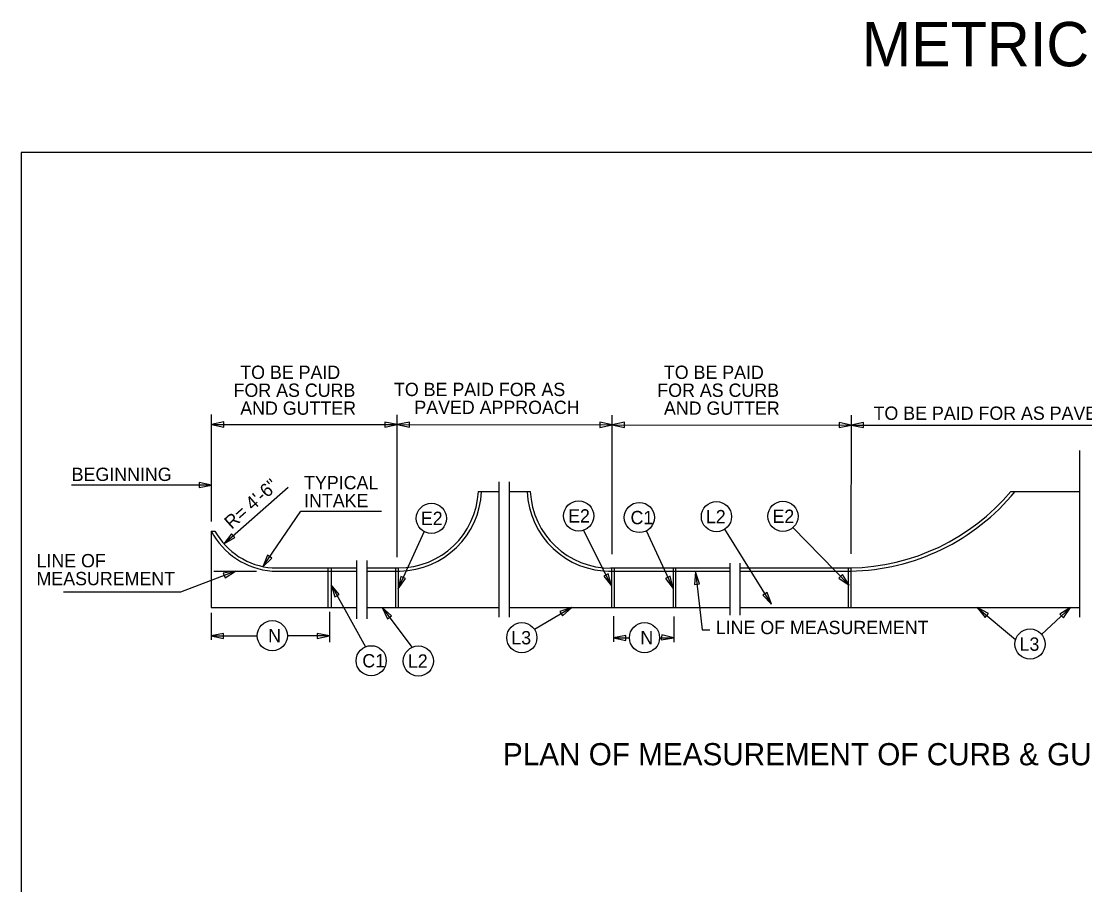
# Model space of a CAD drawing. Extents: x -439.1 to -407.9, y -458.1 to -436.2.
# Drawn here: x -439.11 to -427.13, y -445.93 to -436.2 of the extents above; entities that cross this region are included whole.
import ezdxf

# ---------------------------------------------------------------- set-up
doc = ezdxf.new("R2010")
doc.units = 0
for name, color, linetype in [('Draft_Named_Boundary', 7, 'Continuous'), ('Level 4', 7, 'Continuous'), ('Level 46', 7, 'Continuous')]:
    doc.layers.add(name, color=color, linetype=linetype)

msp = doc.modelspace()

# ---------------------------------------------------------------- linework, layer by layer
at = {"layer": 'Draft_Named_Boundary'}
msp.add_lwpolyline([(-439.109, -458.051), (-407.859, -458.051), (-407.859, -437.676), (-439.109, -437.676)], close=True, dxfattribs=at)
at = {"layer": 'Level 4'}
for p, q in [((-436.966, -441.833), (-436.965, -440.63)), ((-434.875, -442.238), (-434.874, -440.631)), ((-432.453, -442.203), (-432.451, -440.636)), ((-429.76, -442.198), (-429.758, -440.638)), ((-436.965, -440.741), (-434.874, -440.743)), ((-434.874, -440.743), (-432.452, -440.745)), ((-432.452, -440.745), (-429.759, -440.748)), ((-429.759, -440.748), (-424.52, -440.753)), ((-427.187, -441.035), (-427.187, -442.913)), ((-436.965, -441.425), (-438.542, -441.425)), ((-436.827, -442.086), (-436.104, -441.449)), ((-433.728, -441.388), (-433.728, -442.913)), ((-433.613, -441.388), (-433.613, -442.913)), ((-433.962, -441.497), (-433.728, -441.497)), ((-433.613, -441.497), (-433.374, -441.497)), ((-427.962, -441.497), (-427.187, -441.497)), ((-436.389, -442.345), (-435.959, -441.719)), ((-435.959, -441.719), (-435.052, -441.719)), ((-430.657, -442.765), (-431.183, -441.921)), ((-429.783, -442.551), (-430.416, -441.904)), ((-436.971, -441.942), (-436.929, -441.942)), ((-436.969, -441.942), (-436.969, -442.804)), ((-434.863, -442.592), (-434.572, -441.95)), ((-432.459, -442.56), (-432.776, -441.933)), ((-431.767, -442.59), (-432.065, -441.939)), ((-435.333, -442.275), (-435.333, -442.93)), ((-435.218, -442.275), (-435.218, -442.93)), ((-436.695, -442.394), (-437.317, -442.63)), ((-436.939, -442.394), (-436.459, -442.394)), ((-436.283, -442.394), (-435.333, -442.394)), ((-436.281, -442.358), (-435.333, -442.358)), ((-435.656, -442.358), (-435.656, -442.804)), ((-435.619, -442.358), (-435.619, -442.804)), ((-435.218, -442.358), (-434.863, -442.358)), ((-435.218, -442.394), (-434.844, -442.394)), ((-434.892, -442.358), (-434.892, -442.804)), ((-434.892, -442.358), (-434.892, -442.804)), ((-434.863, -442.358), (-434.863, -442.804)), ((-432.494, -442.394), (-431.128, -442.394)), ((-432.473, -442.358), (-431.128, -442.358)), ((-432.459, -442.358), (-432.459, -442.804)), ((-432.431, -442.358), (-432.431, -442.804)), ((-431.767, -442.358), (-431.767, -442.804)), ((-431.738, -442.358), (-431.738, -442.804)), ((-431.514, -442.397), (-431.44, -443.055)), ((-431.128, -442.304), (-431.128, -442.892)), ((-431.013, -442.304), (-431.013, -442.892)), ((-431.013, -442.358), (-429.773, -442.358)), ((-431.013, -442.394), (-429.766, -442.394)), ((-429.794, -442.358), (-429.794, -442.804)), ((-429.766, -442.358), (-429.766, -442.804)), ((-437.317, -442.63), (-438.634, -442.63)), ((-435.619, -442.549), (-435.23, -443.246)), ((-436.969, -442.804), (-435.333, -442.804)), ((-436.969, -442.864), (-436.969, -443.17)), ((-435.637, -442.852), (-435.637, -443.193)), ((-435.218, -442.804), (-433.728, -442.804)), ((-435.045, -442.804), (-434.708, -443.251)), ((-433.613, -442.804), (-431.128, -442.804)), ((-432.908, -442.804), (-433.329, -443.05)), ((-431.013, -442.804), (-427.187, -442.804)), ((-428.34, -442.804), (-427.908, -443.165)), ((-427.291, -442.804), (-427.615, -443.107)), ((-432.438, -442.902), (-432.438, -443.191)), ((-431.758, -442.905), (-431.759, -443.193)), ((-436.969, -443.123), (-436.451, -443.125)), ((-435.637, -443.125), (-436.111, -443.125)), ((-431.44, -443.055), (-431.352, -443.055)), ((-432.438, -443.147), (-432.258, -443.147)), ((-431.918, -443.147), (-431.759, -443.147))]:
    msp.add_line(p, q, dxfattribs=at)
for points in [[(-436.826, -440.713), (-436.965, -440.741), (-436.826, -440.77)], [(-435.012, -440.772), (-434.874, -440.743), (-435.012, -440.714)], [(-434.736, -440.714), (-434.874, -440.743), (-434.736, -440.772)], [(-432.59, -440.774), (-432.452, -440.745), (-432.59, -440.716)], [(-432.313, -440.717), (-432.452, -440.745), (-432.313, -440.774)], [(-429.897, -440.776), (-429.759, -440.748), (-429.897, -440.719)], [(-429.62, -440.719), (-429.759, -440.748), (-429.62, -440.777)], [(-437.104, -441.453), (-436.965, -441.425), (-437.104, -441.396)], [(-436.742, -441.973), (-436.827, -442.086), (-436.704, -442.016)], [(-436.334, -442.214), (-436.389, -442.345), (-436.287, -442.247)], [(-436.814, -442.47), (-436.695, -442.394), (-436.834, -442.416)], [(-431.469, -442.537), (-431.513, -442.402), (-431.526, -442.543)], [(-434.832, -442.454), (-434.863, -442.592), (-434.78, -442.477)], [(-432.547, -442.449), (-432.459, -442.56), (-432.496, -442.423)], [(-431.851, -442.476), (-431.767, -442.59), (-431.798, -442.452)], [(-429.9, -442.473), (-429.783, -442.551), (-429.859, -442.433)], [(-435.527, -442.656), (-435.619, -442.549), (-435.577, -442.684)], [(-430.755, -442.663), (-430.657, -442.765), (-430.706, -442.633)], [(-434.938, -442.897), (-435.045, -442.804), (-434.984, -442.932)], [(-433.013, -442.899), (-432.908, -442.804), (-433.042, -442.849)], [(-428.215, -442.871), (-428.34, -442.804), (-428.252, -442.915)], [(-427.37, -442.921), (-427.291, -442.804), (-427.41, -442.88)], [(-436.831, -443.095), (-436.969, -443.123), (-436.831, -443.152)], [(-435.776, -443.154), (-435.637, -443.125), (-435.776, -443.097)], [(-432.3, -443.119), (-432.438, -443.147), (-432.3, -443.176)], [(-431.899, -443.167), (-431.759, -443.147), (-431.895, -443.11)]]:
    msp.add_lwpolyline(points, close=True, dxfattribs=at)
for centre in [(-434.489, -441.799), (-432.83, -441.772), (-432.146, -441.79), (-431.278, -441.78), (-430.529, -441.776), (-436.281, -443.122), (-433.47, -443.144), (-432.088, -443.144), (-427.745, -443.216), (-435.167, -443.404), (-434.636, -443.407)]:
    msp.add_circle(centre, 0.17, dxfattribs=at)
for centre, radius, start, end in [((-434.864, -441.453), 0.905, 270, 357.253), ((-434.864, -441.453), 0.942, 271.1561, 357.253), ((-432.474, -441.457), 0.938, 182.4182, 270.8273), ((-432.474, -441.457), 0.902, 182.516, 270.873), ((-429.812, -439.941), 2.417, 271.0742, 319.9581), ((-429.812, -439.941), 2.454, 271.0742, 320.6696), ((-436.214, -441.541), 0.856, 207.9105, 265.4036), ((-436.214, -441.541), 0.82, 209.286, 265.4036)]:
    msp.add_arc(centre, radius, start, end, dxfattribs=at)

# ---------------------------------------------------------------- texts
for s, height, p in [('TO BE PAID', 0.15, (-436.642, -440.228)), ('TO BE PAID', 0.15, (-431.87, -440.228)), ('FOR AS CURB', 0.15, (-436.717, -440.43)), ('TO BE PAID FOR AS', 0.15, (-434.91, -440.421)), ('FOR AS CURB', 0.15, (-431.944, -440.43)), ('AND GUTTER', 0.15, (-436.642, -440.632)), ('PAVED APPROACH', 0.15, (-434.681, -440.623)), ('AND GUTTER', 0.15, (-431.869, -440.632)), ('TO BE PAID FOR AS PAVED APPROACH', 0.15, (-429.508, -440.689)), ('BEGINNING', 0.15, (-438.541, -441.378)), ('TYPICAL', 0.15, (-435.923, -441.472)), ('INTAKE', 0.15, (-435.923, -441.674)), ('E2', 0.15, (-434.608, -441.874)), ('E2', 0.15, (-432.949, -441.847)), ('C1', 0.15, (-432.246, -441.865)), ('L2', 0.15, (-431.397, -441.855)), ('E2', 0.15, (-430.647, -441.851)), ('LINE OF', 0.15, (-438.937, -442.351)), ('MEASUREMENT', 0.15, (-438.937, -442.553)), ('LINE OF MEASUREMENT', 0.15, (-431.285, -443.104)), ('N', 0.15, (-436.328, -443.197)), ('L3', 0.15, (-433.589, -443.219)), ('N', 0.15, (-432.135, -443.219)), ('C1', 0.15, (-435.267, -443.479)), ('L2', 0.15, (-434.754, -443.482)), ('PLAN OF MEASUREMENT OF CURB & GUTTER AND JOINT PLAN', 0.25, (-433.683, -444.582))]:
    msp.add_text(s, height=height, dxfattribs=at).set_placement(p)
for s, rotation, p in [('R= 4\'-6"', 41.7, (-436.739, -441.929)), ('L3', 359.8, (-427.864, -443.291))]:
    msp.add_text(s, height=0.15, rotation=rotation, dxfattribs=at).set_placement(p)
at = {"layer": 'Level 46'}
msp.add_text('METRIC - LEVEL 46 - GREEN', height=0.5, dxfattribs=at).set_placement((-429.642, -436.705))

doc.saveas('drawing.dxf')
